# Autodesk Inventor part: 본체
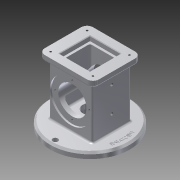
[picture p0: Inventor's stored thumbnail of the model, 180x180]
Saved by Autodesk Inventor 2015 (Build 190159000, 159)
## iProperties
Created: 2019-08
Part Number: 본체
Material: 알루미늄 6061
Document SubType Name: Modeling
Designer: now060
Density: 2.7 g/cm^3
Appearance: 알루미늄 - 평지
Mass: 1038.82 g
Surface Area: 783.569 cm^2
Volume: 384.748 cm^3
Author: now060
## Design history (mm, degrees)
sketch "스케치1"
  geometry: C1 r 67.5 at (0, 0); 1 further point
  constraints: 1 centre point, 1 coincident
  dimensions: "d0" = 135 diameter of C1
extrude "돌출1" new body sketch "스케치1" distance "d1" = 10; taper "d2" = 0 deg
sketch "스케치2"
  geometry: C1 r 67.5 at (0, 0) reference; 3 further points
  constraints: 2 vertical alignment, 1 horizontal alignment
  dimensions: "d3" = 59 distance of C1.centre point (-59, 0); "d4" = 59 distance of C1.centre point (0, 59); "d5" = 59 distance of point (0, -59) C1.centre
hole "구멍1" sketch "스케치2" at (-59, 0), (0, -59), (0, 59) diameter "d6" = 9; stored, may be unused: countersink angle "d10" = 90 deg, drill point angle "d12" = 118 deg; dims "d7" = 6, "d8" = 4, "d9" = 2, "d11" = 8
chamfer "모따기1" distance "d13" = 3; stored, may be unused: second distance "d14" = 2, angle "d15" = 45 deg
sketch "스케치3"
  geometry: C1 r 64.5 at (0, 0) reference; C2 r 59 at (0, 0)
  constraints: 1 centre point, 1 coincident, 1 other
  dimensions: "d16" = 118 diameter of C2
feature "엠보싱1" sketch "스케치3" dims "d17" = 0.5, "d18" = 0
sketch "스케치4"
  geometry: L1 (-37, -33)-(37, -33); L2 (37, -33)-(37, 33); L3 (37, 33)-(-37, 33); L4 (-37, 33)-(-37, -33); C1 r 64.5 at (0, 0) reference
  constraints: 8 end point, 2 parallel, 1 horizontal, 1 perpendicular
  dimensions: "d19" = 74 distance between parallel lines of L4 L2; "d20" = 37 distance from line of L4 C1.centre; "d21" = 66 distance between parallel lines of L3 L1; "d22" = 33 distance from line of L1 C1.centre
extrude "돌출2" join sketch "스케치4" distance "d23" = 88; taper "d24" = 0 deg
sketch "스케치5"
  geometry: L1 (-46, -41)-(46, -41); L2 (46, -41)-(46, 41); L3 (46, 41)-(-46, 41); L4 (-46, 41)-(-46, -41); 1 further point
  constraints: 8 end point, 2 parallel, 1 horizontal, 1 perpendicular
  dimensions: "d25" = 92 distance of L2.end L3.end; "d26" = 46 distance from line of L2 point (0, 0); "d27" = 82 distance between parallel lines of L1 L3; "d28" = 41 distance from line of L1 point (0, 0)
extrude "돌출3" join sketch "스케치5" distance "d29" = 10; taper "d30" = 0 deg
fillet "모깎기1" dims "d31" = 10
sketch "스케치6"
  geometry: A1 r 10 centre (36, 31) between (46, 31) and (36, 41) reference; A2 r 10 centre (-36, 31) between (-36, 41) and (-46, 31) reference; A3 r 10 centre (-36, -31) between (-46, -31) and (-36, -41) reference; A4 r 10 centre (36, -31) between (36, -41) and (46, -31) reference; 1 further point
hole "구멍2" sketch "스케치6" at (-36, -31), (-36, 31), (36, -31), (36, 31) diameter "d32" = 3.242; stored, may be unused: countersink angle "d36" = 90 deg, drill point angle "d38" = 118 deg; dims "d33" = 4, "d34" = 4, "d35" = 2, "d37" = 6
sketch "스케치7"
  geometry: L1 (26, -26)-(-26, -26); L2 (-26, -26)-(-26, 26); L3 (-26, 26)-(26, 26); L4 (26, 26)-(26, -26); L5 (26, -26)-(-26, 26); L6 (-26, -26)-(26, 26); 1 further point
  constraints: 12 end point, 2 midpoint, 2 parallel, 2 perpendicular, 1 horizontal
  dimensions: "d39" = 52 distance of L2.end L3.end
extrude "돌출4" cut sketch "스케치7" distance "d40" = 8; taper "d41" = 0 deg
sketch "스케치8"
  geometry: L1 (22, -22)-(-22, -22); L2 (-22, -22)-(-22, 22); L3 (-22, 22)-(22, 22); L4 (22, 22)-(22, -22); L5 (22, -22)-(-22, 22); L6 (-22, -22)-(22, 22); 1 further point
  constraints: 12 end point, 2 midpoint, 2 parallel, 2 perpendicular, 1 horizontal
  dimensions: "d42" = 44 distance of L2.end L3.end
extrude "돌출5" cut sketch "스케치8" distance "d43" = 74; taper "d44" = 0 deg
fillet "모깎기2" dims "d45" = 3
fillet "모깎기3" dims "d46" = 3
fillet "모깎기4" dims "d47" = 3
fillet "모깎기5" dims "d48" = 3
chamfer "모따기2" distance "d49" = 1; stored, may be unused: second distance "d50" = 2, angle "d51" = 45 deg
sketch "스케치9"
  geometry: L1 (-33.5, -95)-(101.5, -95) reference; C1 r 35 at (34, -41); 1 further point
  constraints: 1 centre point, 1 vertical alignment
  dimensions: "d52" = 70 diameter of C1; "d53" = 54 distance from line of C1.centre L1
extrude "돌출6" cut sketch "스케치9" distance "d54" = 3; taper "d55" = 0 deg
sketch "스케치10"
  geometry: C1 r 35 at (0, 0) reference; 2 further points
  constraints: 1 vertical alignment
  dimensions: "d56" = 29 distance of point (0, 29) C1.centre
hole "구멍3" sketch "스케치10" at (0, 29) diameter "d57" = 3.242; stored, may be unused: countersink angle "d61" = 90 deg, drill point angle "d63" = 118 deg; dims "d58" = 4, "d59" = 4, "d60" = 2, "d62" = 6
sketch "스케치11"
  geometry: C1 r 35 at (0, 0) reference; 1 further point
hole "구멍4" sketch "스케치11" at (0, 0) diameter "d67" = 48; stored, may be unused: countersink angle "d71" = 90 deg, drill point angle "d73" = 118 deg; dims "d68" = 4, "d69" = 4, "d70" = 2, "d72" = 6
sketch "스케치12"
  geometry: C1 r 67.5 at (0, 0) reference
hole "구멍5" sketch "스케치12" at (0, 0) diameter "d74" = 25; stored, may be unused: countersink angle "d78" = 90 deg, drill point angle "d80" = 118 deg; dims "d75" = 4, "d76" = 50, "d77" = 18, "d79" = 6
fillet "모깎기6" dims "d81" = 3
sketch "스케치13"
  geometry: L1 (95, -37.5)-(95, 97.5) reference; 3 further points
  constraints: 2 horizontal alignment
  dimensions: "d82" = 37 distance from line of L1 point (58, 30); "d83" = 43 distance of point (15, 30) point (58, 30)
hole "구멍6" sketch "스케치13" at (15, 30), (58, 30) diameter "d84" = 4.917; stored, may be unused: countersink angle "d88" = 90 deg, drill point angle "d90" = 118 deg; dims "d85" = 12, "d86" = 50, "d87" = 18, "d89" = 48
node "솔리드1"
pattern_circular "원형 패턴1" dims angle "d65" = 360 deg
mirror "대칭1"
